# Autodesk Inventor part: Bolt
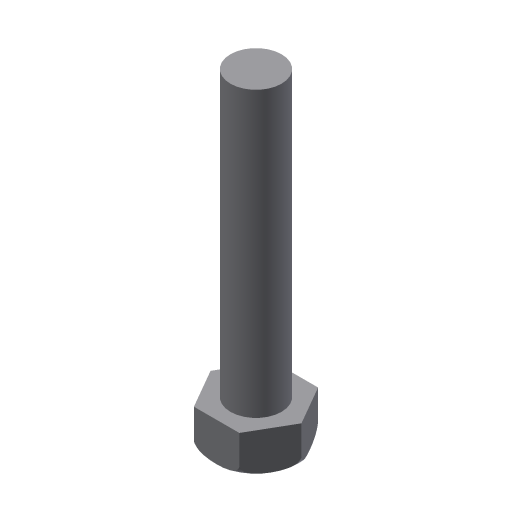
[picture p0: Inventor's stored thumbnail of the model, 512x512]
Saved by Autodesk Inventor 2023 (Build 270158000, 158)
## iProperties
Shininess: 77.0
Length Units: 11269
Angle Units: 11279
Time Units: 11290
Mass Units: 11283
Length Display Precision: 3
Angle Display Precision: 2
Created: 2002-02
Part Number: Bolt
Document SubType Name: Modeling
Designer: ***
Density: 1 g/cm^3
Material: Generic
Appearance: Default
Density: 0.0
Volumn: 0.0
Area: 0.0
PropertySet Name: Model Information
Control State: 0
Master: False
Checked Out: False
Author: ***
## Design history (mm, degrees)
sketch "Sketch1"
  geometry: C1 r 4 at (0, 0)
  constraints: 1 centre point
  dimensions: "d0" = 8 diameter of C1
extrude "Extrusion1" new body sketch "Sketch1" stored distance "d1" = 3.5; taper "d2" = 0 deg
fillet "Fillet1" dims "d3" = 1
sketch "Sketch2"
  geometry: L1 (4, 0)-(2, -3.464); L2 (2, -3.464)-(-2, -3.464); L3 (-2, -3.464)-(-4, 0); L4 (-4, 0)-(-2, 3.464); L5 (-2, 3.464)-(2, 3.464); L6 (2, 3.464)-(4, 0); 2 further points
  constraints: 12 end point, 1 coincident, 11 other
extrude "Extrusion2" sketch "Sketch2" extent not by distance; stored distance "d4" = 3.5; taper "d5" = 0 deg
sketch "Sketch3"
  geometry: C1 r 2.25 at (0, 0)
  constraints: 1 centre point
  dimensions: "d6" = 4.5 diameter of C1
extrude "Extrusion3" join sketch "Sketch3" distance "d7" = 25; taper "d8" = 0 deg
body "Solid1"
